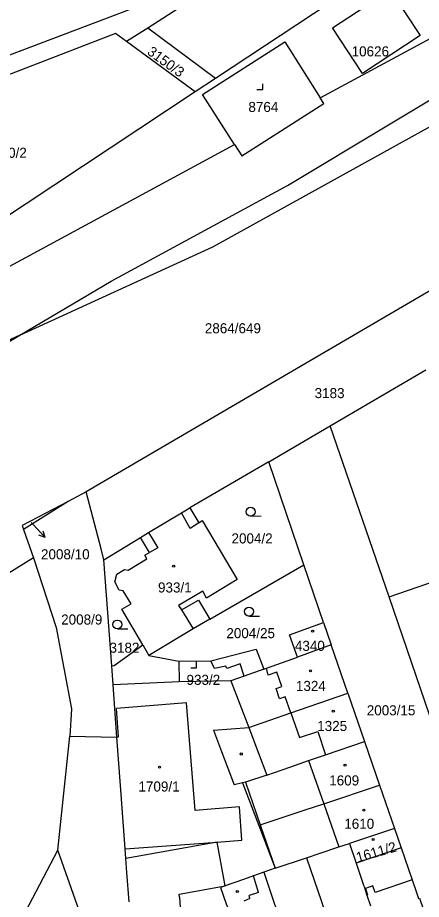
# Model space of a CAD drawing. Extents: x -564952 to -564307, y -1202373 to -1201847.
# Drawn here: x -564479.9 to -564411.7, y -1202086.9 to -1201937.9 of the extents above; entities that cross this region are included whole.
import ezdxf

# ---------------------------------------------------------------- set-up
doc = ezdxf.new("R2010")
doc.units = 0
for name, color, linetype in [('Hranice parcel', 7, 'Continuous'), ('Parcelní čísla', 7, 'Continuous'), ('Pop  PČ popisy', 7, 'Continuous'), ('Vnitřní kresba', 7, 'Continuous'), ('Značky budov', 7, 'Continuous'), ('Značky kultur', 7, 'Continuous')]:
    doc.layers.add(name, color=color, linetype=linetype)

msp = doc.modelspace()

# ---------------------------------------------------------------- linework, layer by layer
at = {"layer": 'Hranice parcel'}
for p, q in [((-564457.9, -1201939.66), (-564461.46, -1201941.96)), ((-564446.42, -1201948.18), (-564457.9, -1201939.66)), ((-564449.87, -1201950.46), (-564461.46, -1201941.96)), ((-564446.42, -1201948.18), (-564449.87, -1201950.46)), ((-564449.87, -1201950.46), (-564494.86, -1201980.19)), ((-564499.17, -1201989.59), (-564443.23, -1201959.33)), ((-564403.97, -1201980.4), (-564468.28, -1202018.06)), ((-564479.51, -1201991.57), (-564490.82, -1201996.75)), ((-564427.05, -1202006.92), (-564410.93, -1201997.4)), ((-564437.42, -1202012.99), (-564427.05, -1202006.92)), ((-564417.13, -1202035.78), (-564427.05, -1202006.92)), ((-564437.42, -1202012.99), (-564450.8, -1202020.74)), ((-564431.52, -1202030.36), (-564437.42, -1202012.99)), ((-564468.28, -1202018.06), (-564471.33, -1202019.66)), ((-564471.33, -1202019.66), (-564478.89, -1202024.39)), ((-564478.89, -1202024.39), (-564477.18, -1202029.23)), ((-564465.33, -1202029.52), (-564459.14, -1202025.77)), ((-564477.18, -1202029.23), (-564490.61, -1202037.43)), ((-564463.97, -1202047.44), (-564465.33, -1202029.52)), ((-564447.43, -1202039.56), (-564431.52, -1202030.36)), ((-564428.18, -1202040.15), (-564431.52, -1202030.36)), ((-564409.49, -1202058.02), (-564417.13, -1202035.78)), ((-564428.18, -1202040.15), (-564426.9, -1202043.9)), ((-564458.73, -1202043.91), (-564457.69, -1202045.7)), ((-564439.59, -1202044.65), (-564438.28, -1202048.03)), ((-564426.9, -1202043.9), (-564432.59, -1202045.97)), ((-564424.11, -1202052.05), (-564426.9, -1202043.9)), ((-564463.72, -1202050.66), (-564463.97, -1202047.44)), ((-564463.09, -1202059.5), (-564463.72, -1202050.66)), ((-564443.84, -1202049.99), (-564440.84, -1202057.87)), ((-564424.11, -1202052.05), (-564421.27, -1202060.22)), ((-564473.1, -1202078.61), (-564471.03, -1202059.34)), ((-564471.03, -1202059.34), (-564463.09, -1202059.5)), ((-564421.27, -1202060.22), (-564418.71, -1202067.61)), ((-564418.71, -1202067.61), (-564416.18, -1202074.92)), ((-564438.91, -1202074.33), (-564436.39, -1202081.67)), ((-564416.18, -1202074.92), (-564423.8, -1202077.47)), ((-564416.18, -1202074.92), (-564415.05, -1202078.24)), ((-564446.17, -1202077.23), (-564461.59, -1202080.01)), ((-564444.84, -1202084.65), (-564446.17, -1202077.23)), ((-564425.59, -1202078.07), (-564423.8, -1202077.47)), ((-564423.8, -1202077.47), (-564422.67, -1202080.83)), ((-564415.05, -1202078.24), (-564422.67, -1202080.83)), ((-564436.39, -1202081.67), (-564431.09, -1202079.9)), ((-564436.39, -1202081.67), (-564438.3, -1202082.34))]:
    msp.add_line(p, q, dxfattribs=at)
for points in [[(-564328.21, -1201853.59), (-564368.6, -1201879.82), (-564418.44, -1201912.36), (-564448.23, -1201931.71), (-564529.16, -1201962.4)], [(-564348.82, -1201871.01), (-564402.54, -1201903.93), (-564457.9, -1201939.66)], [(-564341.58, -1201883.31), (-564399.74, -1201917.34), (-564446.42, -1201948.18)], [(-564428.74, -1201951.43), (-564393.56, -1201932.42), (-564314.65, -1201888.26)], [(-564479.51, -1201991.57), (-564446.91, -1201976.65), (-564359.6, -1201928.27)], [(-564426.66, -1201939.6), (-564416.96, -1201933.2), (-564411.87, -1201940.91), (-564421.6, -1201947.33), (-564426.66, -1201939.6)], [(-564479.51, -1201991.57), (-564464.1, -1201982.45), (-564434.29, -1201966.3), (-564383.08, -1201935.53)], [(-564461.46, -1201941.96), (-564463.36, -1201940.57), (-564498.95, -1201954.33), (-564512.2, -1201972.88), (-564507.01, -1201978.45), (-564501.74, -1201973.64), (-564494.86, -1201980.19)], [(-564443.23, -1201959.33), (-564448.62, -1201950.87), (-564434.71, -1201942.01), (-564428.74, -1201951.43)], [(-564443.23, -1201959.33), (-564442.01, -1201961.25), (-564428.12, -1201952.41), (-564428.74, -1201951.43)], [(-564490.82, -1201996.75), (-564486.65, -1201995.79), (-564479.51, -1201991.57)], [(-564465.33, -1202029.52), (-564465.75, -1202027.69), (-564468.28, -1202018.06)], [(-564471.33, -1202019.66), (-564479.12, -1202023.74), (-564478.89, -1202024.39)], [(-564459.14, -1202025.77), (-564457.77, -1202024.94), (-564452.21, -1202021.57), (-564450.8, -1202020.74)], [(-564450.8, -1202020.74), (-564449.25, -1202023.27), (-564448.68, -1202022.89), (-564442.78, -1202032.89), (-564447.94, -1202036.01)], [(-564458.73, -1202043.91), (-564462.25, -1202037.9), (-564460.72, -1202036.98), (-564462.06, -1202034.79), (-564462.7, -1202034.64), (-564463.48, -1202033.26), (-564463.13, -1202031.94), (-564461.84, -1202031.18), (-564461.19, -1202031.3), (-564458.02, -1202029.39), (-564458.41, -1202028.77), (-564457.6, -1202028.31), (-564459.14, -1202025.77)], [(-564477.18, -1202029.23), (-564473.35, -1202040.99), (-564470.75, -1202054.71), (-564471.03, -1202059.34)], [(-564417.13, -1202035.78), (-564404.38, -1202031.4), (-564402.49, -1202037.11), (-564404.61, -1202037.8), (-564399, -1202054.61)], [(-564447.94, -1202036.01), (-564448.6, -1202034.83), (-564452.67, -1202037.25)], [(-564452.67, -1202037.25), (-564452.2, -1202038), (-564449.3, -1202036.37), (-564447.43, -1202039.56)], [(-564447.43, -1202039.56), (-564450.23, -1202041.18), (-564457.69, -1202045.7)], [(-564432.59, -1202045.97), (-564433.95, -1202042.21), (-564428.18, -1202040.15)], [(-564463.97, -1202047.44), (-564463.59, -1202047.41), (-564458.73, -1202043.91)], [(-564457.69, -1202045.7), (-564452.64, -1202046.68), (-564447.24, -1202046.59), (-564439.59, -1202044.65)], [(-564438.28, -1202048.03), (-564437.84, -1202047.87), (-564432.59, -1202045.97)], [(-564438.28, -1202048.03), (-564441.59, -1202049.19), (-564443.84, -1202049.99)], [(-564443.84, -1202049.99), (-564452.56, -1202050.17), (-564463.72, -1202050.66)], [(-564440.84, -1202057.87), (-564433.71, -1202055.4), (-564424.11, -1202052.05)], [(-564440.84, -1202057.87), (-564439.18, -1202062.21), (-564437.78, -1202065.92)], [(-564461.59, -1202080.01), (-564461.7, -1202078.41), (-564462.49, -1202067.67), (-564463.09, -1202059.5)], [(-564437.78, -1202065.92), (-564433.9, -1202064.57), (-564430.75, -1202063.48), (-564427.86, -1202062.5), (-564421.27, -1202060.22)], [(-564437.78, -1202065.92), (-564441.39, -1202067.14), (-564438.91, -1202074.33)], [(-564438.91, -1202074.33), (-564431.27, -1202071.8), (-564428.17, -1202070.77), (-564418.71, -1202067.61)], [(-564431.09, -1202079.9), (-564428.76, -1202079.13), (-564425.59, -1202078.07)], [(-564471.12, -1202112.99), (-564472.91, -1202112.19), (-564480.33, -1202092.49), (-564473.1, -1202078.61)], [(-564471.12, -1202112.99), (-564459.11, -1202118.17), (-564473.1, -1202078.61)], [(-564415.05, -1202078.24), (-564413.23, -1202083.63), (-564412.56, -1202085.59)], [(-564461.05, -1202087.35), (-564461.41, -1202082.39), (-564461.59, -1202080.01)], [(-564431.09, -1202079.9), (-564428.53, -1202087.31), (-564428.23, -1202088.2), (-564427.46, -1202090.41)], [(-564422.67, -1202080.83), (-564421.43, -1202084.51), (-564421.35, -1202084.76)], [(-564438.3, -1202082.34), (-564440.05, -1202082.96), (-564441.73, -1202083.55), (-564444.84, -1202084.65)], [(-564438.3, -1202082.34), (-564437.33, -1202085.18), (-564435.44, -1202090.73), (-564434.73, -1202092.8)], [(-564444.84, -1202084.65), (-564445.61, -1202084.93), (-564444.62, -1202087.67), (-564444.37, -1202088.37)], [(-564421.35, -1202084.76), (-564420.86, -1202086.21), (-564420.25, -1202088.03)], [(-564412.56, -1202085.59), (-564412.16, -1202086.79), (-564411.96, -1202086.73), (-564409.17, -1202094.97)]]:
    msp.add_lwpolyline(points, dxfattribs=at)
at = {"layer": 'Pop  PČ popisy'}
for p, q in [((-564477.59, -1202023.24), (-564477.27, -1202023.57)), ((-564477.27, -1202023.57), (-564475.22, -1202025.77)), ((-564475.22, -1202025.77), (-564476.27, -1202025.37)), ((-564475.22, -1202025.77), (-564475.54, -1202024.69))]:
    msp.add_line(p, q, dxfattribs=at)
at = {"layer": 'Vnitřní kresba'}
for p, q in [((-564450.71, -1202024.23), (-564452.21, -1202021.57)), ((-564449.25, -1202023.27), (-564450.71, -1202024.23)), ((-564457.77, -1202024.94), (-564456.17, -1202027.51)), ((-564456.17, -1202027.51), (-564457.6, -1202028.31)), ((-564452.2, -1202038), (-564450.23, -1202041.18)), ((-564452.64, -1202046.68), (-564452.56, -1202050.17)), ((-564446.59, -1202047.92), (-564447.24, -1202046.59)), ((-564444.69, -1202047.52), (-564446.59, -1202047.92)), ((-564444.52, -1202047.88), (-564444.69, -1202047.52)), ((-564442.27, -1202047.09), (-564444.52, -1202047.88)), ((-564441.59, -1202049.19), (-564442.27, -1202047.09)), ((-564437.53, -1202049.02), (-564437.84, -1202047.87)), ((-564436.08, -1202048.53), (-564437.53, -1202049.02)), ((-564435.24, -1202050.97), (-564436.08, -1202048.53)), ((-564436.21, -1202051.3), (-564435.24, -1202050.97)), ((-564435.61, -1202053.02), (-564436.21, -1202051.3)), ((-564434.65, -1202052.69), (-564435.61, -1202053.02)), ((-564433.71, -1202055.4), (-564434.65, -1202052.69)), ((-564451.37, -1202053.69), (-564463.17, -1202054.64)), ((-564449.9, -1202071.89), (-564451.37, -1202053.69)), ((-564462.81, -1202059.48), (-564463.17, -1202054.64)), ((-564433.71, -1202055.4), (-564432.26, -1202059.59)), ((-564446.8, -1202058.31), (-564440.84, -1202057.87)), ((-564446.8, -1202058.31), (-564445.42, -1202061.93)), ((-564432.26, -1202059.59), (-564429.18, -1202058.53)), ((-564429.18, -1202058.53), (-564427.86, -1202062.5)), ((-564463.09, -1202059.5), (-564462.81, -1202059.48)), ((-564445.42, -1202061.93), (-564443.27, -1202067.56)), ((-564430.75, -1202063.48), (-564428.17, -1202070.77)), ((-564441.89, -1202067.25), (-564443.27, -1202067.56)), ((-564441.39, -1202067.14), (-564441.89, -1202067.25)), ((-564441.89, -1202067.25), (-564436.39, -1202081.67)), ((-564442.41, -1202071.28), (-564449.9, -1202071.89)), ((-564441.98, -1202076.91), (-564442.41, -1202071.28)), ((-564428.17, -1202070.77), (-564425.59, -1202078.07)), ((-564461.7, -1202078.41), (-564446.17, -1202077.23)), ((-564446.17, -1202077.23), (-564441.98, -1202076.91)), ((-564439.17, -1202085.79), (-564440.05, -1202082.96)), ((-564413.23, -1202083.63), (-564419.48, -1202085.74)), ((-564452.59, -1202086.05), (-564444.84, -1202084.65)), ((-564419.85, -1202084.66), (-564421.13, -1202085.09)), ((-564421.13, -1202085.09), (-564420.76, -1202086.18)), ((-564419.48, -1202085.74), (-564419.85, -1202084.66)), ((-564452.55, -1202086.54), (-564452.59, -1202086.05)), ((-564452.55, -1202086.54), (-564452.4, -1202088.31)), ((-564440.63, -1202086.8), (-564441.64, -1202087.22)), ((-564439.17, -1202085.79), (-564440.76, -1202086.29)), ((-564440.63, -1202086.8), (-564440.76, -1202086.29)), ((-564420.76, -1202086.18), (-564420.86, -1202086.21))]:
    msp.add_line(p, q, dxfattribs=at)
at = {"layer": 'Značky budov'}
for centre in [(-564453.51, -1202030.61), (-564430.04, -1202041.59), (-564430.41, -1202048.29), (-564426.54, -1202055.11), (-564442.09, -1202062.36), (-564455.9, -1202064.58), (-564424.56, -1202064.23), (-564421.4, -1202071.86), (-564419.82, -1202076.82), (-564442.76, -1202085.61)]:
    msp.add_circle(centre, 0.175, dxfattribs=at)
at = {"layer": 'Značky kultur'}
for p, q in [((-564438.46, -1201950.07), (-564438.46, -1201949.07)), ((-564439.46, -1201950.07), (-564438.46, -1201950.07)), ((-564440.49, -1202022.16), (-564438.74, -1202022.1)), ((-564440.79, -1202039.04), (-564439.04, -1202039.04)), ((-564463.03, -1202041.21), (-564461.28, -1202041.21)), ((-564449.63, -1202047.78), (-564449.63, -1202046.78)), ((-564450.63, -1202047.78), (-564449.63, -1202047.78))]:
    msp.add_line(p, q, dxfattribs=at)
for centre in [(-564440.52, -1202021.41), (-564440.79, -1202038.29), (-564463.03, -1202040.46)]:
    msp.add_circle(centre, 0.75, dxfattribs=at)

# ---------------------------------------------------------------- texts
at = {"layer": 'Parcelní čísla'}
for s, rotation, p in [('3150/3', 324, (-564458.12, -1201943.99)), ('1611/2', 16, (-564422.41, -1202080.7))]:
    msp.add_text(s, height=1.7, rotation=rotation, dxfattribs=at).set_placement(p)
for s, p in [('10626', (-564423.45, -1201944.45)), ('8764', (-564440.89, -1201953.85)), ('3150/2', (-564485.28, -1201961.59)), ('2864/649', (-564448.25, -1201991.25)), ('3183', (-564429.7, -1202002.21)), ('2004/2', (-564443.74, -1202026.77)), ('2008/10', (-564475.93, -1202029.45)), ('933/1', (-564456.16, -1202035.06)), ('2008/9', (-564472.52, -1202040.48)), ('2004/25', (-564444.61, -1202042.78)), ('3182', (-564464.35, -1202045.24)), ('4340', (-564433.03, -1202044.93)), ('933/2', (-564451.34, -1202050.67)), ('1324', (-564432.86, -1202051.7)), ('2003/15', (-564420.89, -1202055.82)), ('1325', (-564429.26, -1202058.47)), ('1609', (-564427.23, -1202067.67)), ('1709/1', (-564459.46, -1202068.7)), ('1610', (-564424.69, -1202075))]:
    msp.add_text(s, height=1.7, dxfattribs=at).set_placement(p)

doc.saveas('drawing.dxf')
